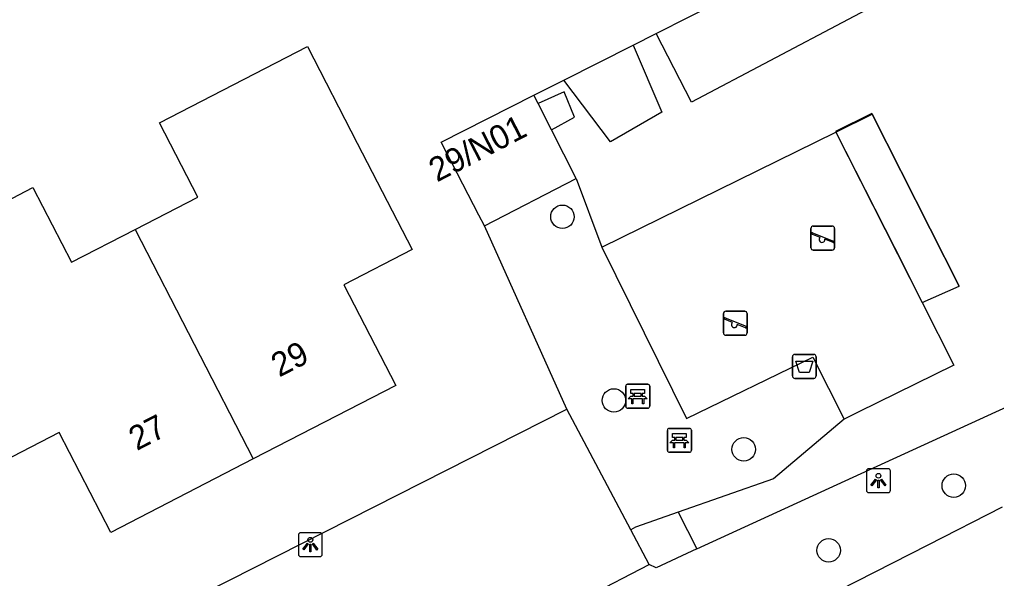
# Model space of a CAD drawing. Extents: x 162722 to 165099, y 384721 to 386283.
# Drawn here: x 163916.12 to 163956.87, y 385059.77 to 385083.1 of the extents above; entities that cross this region are included whole.
import ezdxf

# ---------------------------------------------------------------- set-up
doc = ezdxf.new("R2010")
doc.units = 0
for name, color, linetype in [('IMGEO_Afvalbak', 7, 'Continuous'), ('IMGEO_Bank', 7, 'Continuous'), ('IMGEO_Boom', 7, 'Continuous'), ('IMGEO_Groenvoorziening', 7, 'Continuous'), ('IMGEO_Haag', 7, 'Continuous'), ('IMGEO_Lichtpunt', 7, 'Continuous'), ('IMGEO_Pand', 7, 'Continuous'), ('IMGEO_Pand_nummerreeks', 7, 'Continuous'), ('IMGEO_Parkeervlak_open', 7, 'Continuous'), ('IMGEO_Speelvoorziening', 7, 'Continuous'), ('IMGEO_Voetpad_open', 7, 'Continuous')]:
    doc.layers.add(name, color=color, linetype=linetype)

msp = doc.modelspace()

# ---------------------------------------------------------------- linework, layer by layer
at = {"layer": 'IMGEO_Afvalbak'}
for p, q in [((163948.359, 385068.222), (163948.359, 385069.022)), ((163948.359, 385069.022), (163948.359, 385068.222)), ((163948.459, 385069.122), (163949.249, 385069.122)), ((163949.249, 385069.122), (163948.459, 385069.122)), ((163949.349, 385069.022), (163949.349, 385068.222)), ((163949.349, 385068.222), (163949.349, 385069.022)), ((163949.249, 385068.122), (163948.459, 385068.122)), ((163948.459, 385068.122), (163949.249, 385068.122))]:
    msp.add_line(p, q, dxfattribs=at)
msp.add_lwpolyline([(163948.502, 385068.836), (163949.206, 385068.836), (163949.057, 385068.366), (163948.651, 385068.366), (163948.502, 385068.836)], dxfattribs=at)
for centre, start, end in [((163948.459, 385069.022), 90, 180), ((163948.459, 385069.022), 90, 180), ((163949.249, 385069.022), 0, 90), ((163949.249, 385069.022), 360, 90), ((163948.459, 385068.222), 180, 270), ((163948.459, 385068.222), 180, 270), ((163949.249, 385068.222), 270, 0), ((163949.249, 385068.222), 270, 0)]:
    msp.add_arc(centre, 0.1, start, end, dxfattribs=at)
at = {"layer": 'IMGEO_Bank'}
for p, q in [((163941.406, 385066.951), (163941.406, 385067.792)), ((163941.406, 385067.792), (163941.406, 385066.951)), ((163941.481, 385067.876), (163942.322, 385067.876)), ((163942.322, 385067.876), (163941.481, 385067.876)), ((163942.406, 385067.801), (163942.406, 385066.96)), ((163942.406, 385066.96), (163942.406, 385067.801)), ((163942.103, 385067.274), (163941.71, 385067.274)), ((163941.715, 385067.382), (163941.715, 385067.488)), ((163941.759, 385067.488), (163941.759, 385067.382)), ((163942.047, 385067.494), (163941.765, 385067.494)), ((163941.765, 385067.376), (163942.047, 385067.376)), ((163942.053, 385067.382), (163942.053, 385067.488)), ((163942.097, 385067.488), (163942.097, 385067.382)), ((163942.331, 385066.876), (163941.49, 385066.876)), ((163941.49, 385066.876), (163942.331, 385066.876)), ((163943.144, 385065.111), (163943.144, 385065.952)), ((163943.144, 385065.952), (163943.144, 385065.111)), ((163943.219, 385066.036), (163944.06, 385066.036)), ((163944.06, 385066.036), (163943.219, 385066.036)), ((163944.144, 385065.961), (163944.144, 385065.12)), ((163944.144, 385065.12), (163944.144, 385065.961)), ((163943.453, 385065.542), (163943.453, 385065.648)), ((163943.497, 385065.648), (163943.497, 385065.542)), ((163943.785, 385065.654), (163943.503, 385065.654)), ((163943.503, 385065.536), (163943.785, 385065.536)), ((163943.791, 385065.542), (163943.791, 385065.648)), ((163943.835, 385065.648), (163943.835, 385065.542)), ((163943.841, 385065.434), (163943.448, 385065.434)), ((163944.069, 385065.036), (163943.228, 385065.036)), ((163943.228, 385065.036), (163944.069, 385065.036))]:
    msp.add_line(p, q, dxfattribs=at)
for points in [[(163941.709, 385067.494), (163941.623, 385067.494), (163941.623, 385067.655), (163942.186, 385067.655), (163942.186, 385067.494), (163942.103, 385067.494)], [(163941.653, 385067.274), (163941.511, 385067.274), (163941.623, 385067.376), (163941.709, 385067.376)], [(163941.703, 385067.267), (163941.703, 385067.06), (163941.66, 385067.06), (163941.66, 385067.267)], [(163942.103, 385067.376), (163942.186, 385067.376), (163942.298, 385067.274), (163942.159, 385067.274)], [(163942.153, 385067.267), (163942.153, 385067.06), (163942.109, 385067.06), (163942.109, 385067.267)], [(163943.391, 385065.434), (163943.249, 385065.434), (163943.361, 385065.536), (163943.447, 385065.536)], [(163943.447, 385065.654), (163943.361, 385065.654), (163943.361, 385065.815), (163943.924, 385065.815), (163943.924, 385065.654), (163943.841, 385065.654)], [(163943.841, 385065.536), (163943.924, 385065.536), (163944.036, 385065.434), (163943.897, 385065.434)], [(163943.441, 385065.427), (163943.441, 385065.22), (163943.398, 385065.22), (163943.398, 385065.427)], [(163943.891, 385065.427), (163943.891, 385065.22), (163943.847, 385065.22), (163943.847, 385065.427)]]:
    msp.add_lwpolyline(points, dxfattribs=at)
for centre, radius, start, end in [((163941.484, 385067.798), 0.0779, 92.4484, 184.2845), ((163941.484, 385067.798), 0.0779, 92.4484, 184.2845), ((163942.328, 385067.798), 0.0779, 2.4484, 94.2845), ((163942.328, 385067.798), 0.0779, 2.4484, 94.2845), ((163941.653, 385067.267), 0.00671, 2.8957, 87.1043), ((163941.71, 385067.267), 0.00671, 92.8957, 177.1043), ((163941.708, 385067.487), 0.00671, 2.8957, 87.1043), ((163941.708, 385067.383), 0.00671, 272.8957, 357.1043), ((163941.765, 385067.487), 0.00671, 92.8957, 177.1043), ((163941.765, 385067.383), 0.00671, 182.8957, 267.1043), ((163942.047, 385067.487), 0.00671, 2.8957, 87.1043), ((163942.047, 385067.383), 0.00671, 272.8957, 357.1043), ((163942.104, 385067.487), 0.00671, 92.8957, 177.1043), ((163942.104, 385067.383), 0.00671, 182.8957, 267.1043), ((163942.102, 385067.267), 0.00671, 2.8957, 87.1043), ((163942.159, 385067.267), 0.00671, 92.8957, 177.1043), ((163941.484, 385066.954), 0.0779, 182.4484, 274.2845), ((163941.484, 385066.954), 0.0779, 182.4484, 274.2845), ((163942.328, 385066.954), 0.0779, 272.4484, 4.2845), ((163942.328, 385066.954), 0.0779, 272.4484, 4.2845), ((163943.222, 385065.958), 0.0779, 92.4484, 184.2845), ((163943.222, 385065.958), 0.0779, 92.4484, 184.2845), ((163944.066, 385065.958), 0.0779, 2.4484, 94.2845), ((163944.066, 385065.958), 0.0779, 2.4484, 94.2845), ((163943.446, 385065.647), 0.00671, 2.8957, 87.1043), ((163943.446, 385065.543), 0.00671, 272.8957, 357.1043), ((163943.503, 385065.647), 0.00671, 92.8957, 177.1043), ((163943.503, 385065.543), 0.00671, 182.8957, 267.1043), ((163943.785, 385065.647), 0.00671, 2.8957, 87.1043), ((163943.785, 385065.543), 0.00671, 272.8957, 357.1043), ((163943.842, 385065.647), 0.00671, 92.8957, 177.1043), ((163943.842, 385065.543), 0.00671, 182.8957, 267.1043), ((163943.391, 385065.427), 0.00671, 2.8957, 87.1043), ((163943.448, 385065.427), 0.00671, 92.8957, 177.1043), ((163943.84, 385065.427), 0.00671, 2.8957, 87.1043), ((163943.897, 385065.427), 0.00671, 92.8957, 177.1043), ((163943.222, 385065.114), 0.0779, 182.4484, 274.2845), ((163943.222, 385065.114), 0.0779, 182.4484, 274.2845), ((163944.066, 385065.114), 0.0779, 272.4484, 4.2845), ((163944.066, 385065.114), 0.0779, 272.4484, 4.2845)]:
    msp.add_arc(centre, radius, start, end, dxfattribs=at)
at = {"layer": 'IMGEO_Boom'}
for centre in [(163938.763, 385074.866), (163940.912, 385067.202), (163946.327, 385065.16), (163955.089, 385063.644), (163949.869, 385060.944)]:
    msp.add_circle(centre, 0.489, dxfattribs=at)
at = {"layer": 'IMGEO_Groenvoorziening'}
for points in [[(163953.947, 385084.839), (163944.148, 385079.652), (163942.681, 385082.519)], [(163942.681, 385082.519), (163945.427, 385083.907)], [(163941.712, 385082.029), (163942.681, 385082.519)], [(163938.823, 385080.568), (163941.712, 385082.029)], [(163941.712, 385082.029), (163942.908, 385079.238), (163940.769, 385077.997), (163938.823, 385080.568)], [(163937.574, 385079.937), (163938.823, 385080.568)], [(163950.173, 385078.399), (163951.683, 385079.142), (163955.32, 385071.967)], [(163940.409, 385073.595), (163950.173, 385078.399)], [(163950.173, 385078.399), (163950.173, 385078.399)], [(163950.173, 385078.399), (163953.776, 385071.287)], [(163939.334, 385076.457), (163940.409, 385073.595)], [(163938.946, 385066.833), (163935.508, 385074.482)], [(163940.409, 385073.595), (163943.946, 385066.445), (163949.212, 385069.011), (163950.523, 385066.423)], [(163953.776, 385071.287), (163955.099, 385068.674), (163951.1, 385066.707), (163950.523, 385066.423)], [(163944.367, 385061.012), (163952.229, 385064.609), (163966.391, 385071.088), (163968.192, 385068.42)], [(163950.523, 385066.423), (163947.565, 385063.927), (163943.589, 385062.535)]]:
    msp.add_lwpolyline(points, dxfattribs=at)
at = {"layer": 'IMGEO_Haag'}
for points in [[(163955.32, 385071.967), (163951.668, 385079.172), (163950.161, 385078.423), (163950.173, 385078.399)], [(163950.173, 385078.399), (163952.614, 385073.581), (163953.776, 385071.287)], [(163953.776, 385071.287), (163955.32, 385071.967)]]:
    msp.add_lwpolyline(points, dxfattribs=at)
at = {"layer": 'IMGEO_Lichtpunt'}
for p, q in [((163952.351, 385064.353), (163951.543, 385064.353)), ((163952.351, 385064.353), (163951.543, 385064.353)), ((163951.449, 385064.258), (163951.449, 385063.451)), ((163951.449, 385064.258), (163951.449, 385063.451)), ((163952.445, 385063.451), (163952.445, 385064.258)), ((163952.445, 385063.451), (163952.445, 385064.258)), ((163951.543, 385063.357), (163952.351, 385063.357)), ((163951.543, 385063.357), (163952.351, 385063.357)), ((163927.748, 385061.586), (163927.748, 385060.779)), ((163927.748, 385061.586), (163927.748, 385060.779)), ((163928.65, 385061.681), (163927.842, 385061.681)), ((163928.65, 385061.681), (163927.842, 385061.681)), ((163928.744, 385060.779), (163928.744, 385061.586)), ((163928.744, 385060.779), (163928.744, 385061.586)), ((163927.842, 385060.685), (163928.65, 385060.685)), ((163927.842, 385060.685), (163928.65, 385060.685))]:
    msp.add_line(p, q, dxfattribs=at)
for points in [[(163951.823, 385063.922), (163951.862, 385063.894), (163951.674, 385063.632), (163951.636, 385063.659), (163951.823, 385063.922)], [(163952.035, 385063.894), (163952.073, 385063.921), (163952.26, 385063.659), (163952.221, 385063.631), (163952.035, 385063.894)], [(163951.925, 385063.874), (163951.972, 385063.874), (163951.972, 385063.552), (163951.925, 385063.552), (163951.925, 385063.874)], [(163928.122, 385061.25), (163928.161, 385061.222), (163927.973, 385060.96), (163927.935, 385060.987), (163928.122, 385061.25)], [(163928.224, 385061.202), (163928.271, 385061.202), (163928.271, 385060.88), (163928.224, 385060.88), (163928.224, 385061.202)], [(163928.334, 385061.222), (163928.372, 385061.249), (163928.559, 385060.987), (163928.52, 385060.959), (163928.334, 385061.222)]]:
    msp.add_lwpolyline(points, dxfattribs=at)
for centre in [(163951.948, 385064.056), (163928.247, 385061.384)]:
    msp.add_circle(centre, 0.0994, dxfattribs=at)
for centre, start, end in [((163951.543, 385064.258), 90, 180), ((163951.543, 385064.258), 90, 180), ((163952.351, 385064.258), 0, 90), ((163952.351, 385064.258), 0, 90), ((163951.543, 385063.451), 180, 270), ((163951.543, 385063.451), 180, 270), ((163952.351, 385063.451), 270, 0), ((163952.351, 385063.451), 270, 360), ((163927.842, 385061.586), 90, 180), ((163927.842, 385061.586), 90, 180), ((163928.65, 385061.586), 0, 90), ((163928.65, 385061.586), 0, 90), ((163927.842, 385060.779), 180, 270), ((163927.842, 385060.779), 180, 270), ((163928.65, 385060.779), 270, 0), ((163928.65, 385060.779), 270, 360)]:
    msp.add_arc(centre, 0.0946, start, end, dxfattribs=at)
at = {"layer": 'IMGEO_Pand'}
for points in [[(163920.934, 385074.332), (163923.551, 385075.682), (163921.948, 385078.788), (163928.127, 385081.975), (163930.207, 385077.941), (163932.499, 385073.497), (163929.642, 385072.024), (163931.809, 385067.822), (163925.868, 385064.758)], [(163935.508, 385074.482), (163935.277, 385074.929), (163933.702, 385077.979), (163937.574, 385079.937)], [(163937.748, 385079.592), (163937.574, 385079.937)], [(163938.305, 385078.491), (163937.748, 385079.592)], [(163939.334, 385076.457), (163938.305, 385078.491)], [(163935.508, 385074.482), (163939.334, 385076.457)], [(163925.868, 385064.758), (163919.927, 385061.695), (163917.775, 385065.867), (163914.617, 385064.238), (163910.224, 385072.757), (163914.668, 385075.049), (163916.677, 385076.085), (163918.286, 385072.966), (163920.934, 385074.332)], [(163920.934, 385074.332), (163925.868, 385064.758)], [(163957.108, 385062.751), (163954.007, 385061.166), (163949.555, 385058.889)]]:
    msp.add_lwpolyline(points, dxfattribs=at)
at = {"layer": 'IMGEO_Parkeervlak_open'}
for points in [[(163906.693, 385073.366), (163915.816, 385055.107), (163938.946, 385066.833)], [(163941.615, 385061.804), (163938.946, 385066.833)], [(163940.84, 385056.735), (163939.815, 385059.02), (163942.387, 385060.349)]]:
    msp.add_lwpolyline(points, dxfattribs=at)
at = {"layer": 'IMGEO_Speelvoorziening'}
for p, q in [((163949.131, 385073.576), (163949.131, 385074.376)), ((163949.131, 385074.376), (163949.131, 385073.576)), ((163949.514, 385074.004), (163949.175, 385074.141)), ((163949.2, 385074.201), (163950.076, 385073.848)), ((163949.231, 385074.476), (163950.021, 385074.476)), ((163950.021, 385074.476), (163949.231, 385074.476)), ((163950.121, 385074.376), (163950.121, 385073.576)), ((163950.121, 385073.576), (163950.121, 385074.376)), ((163950.052, 385073.788), (163949.712, 385073.925)), ((163950.021, 385073.476), (163949.231, 385073.476)), ((163949.231, 385073.476), (163950.021, 385073.476)), ((163945.579, 385070.923), (163946.369, 385070.923)), ((163946.369, 385070.923), (163945.579, 385070.923)), ((163945.479, 385070.023), (163945.479, 385070.823)), ((163945.479, 385070.823), (163945.479, 385070.023)), ((163945.862, 385070.451), (163945.523, 385070.588)), ((163945.548, 385070.648), (163946.424, 385070.295)), ((163946.469, 385070.823), (163946.469, 385070.023)), ((163946.469, 385070.023), (163946.469, 385070.823)), ((163946.4, 385070.235), (163946.06, 385070.372)), ((163946.369, 385069.923), (163945.579, 385069.923)), ((163945.579, 385069.923), (163946.369, 385069.923))]:
    msp.add_line(p, q, dxfattribs=at)
for centre, radius, start, end in [((163949.231, 385074.376), 0.1, 90, 180), ((163949.231, 385074.376), 0.1, 90, 180), ((163949.188, 385074.171), 0.0327, 68.078, 248.078), ((163950.021, 385074.376), 0.1, 0, 90), ((163950.021, 385074.376), 0.1, 360, 90), ((163949.593, 385073.914), 0.12, 130.9928, 5.1632), ((163950.064, 385073.818), 0.0327, 248.078, 68.078), ((163949.231, 385073.576), 0.1, 180, 270), ((163949.231, 385073.576), 0.1, 180, 270), ((163950.021, 385073.576), 0.1, 270, 0), ((163950.021, 385073.576), 0.1, 270, 0), ((163945.579, 385070.823), 0.1, 90, 180), ((163945.579, 385070.823), 0.1, 90, 180), ((163946.369, 385070.823), 0.1, 0, 90), ((163946.369, 385070.823), 0.1, 360, 90), ((163945.536, 385070.618), 0.0327, 68.078, 248.078), ((163945.941, 385070.361), 0.12, 130.9928, 5.1632), ((163945.579, 385070.023), 0.1, 180, 270), ((163945.579, 385070.023), 0.1, 180, 270), ((163946.369, 385070.023), 0.1, 270, 0), ((163946.369, 385070.023), 0.1, 270, 0), ((163946.412, 385070.265), 0.0327, 248.078, 68.078)]:
    msp.add_arc(centre, radius, start, end, dxfattribs=at)
at = {"layer": 'IMGEO_Voetpad_open'}
for points in [[(163938.305, 385078.491), (163939.27, 385079.029), (163938.843, 385080.073), (163937.748, 385079.592)], [(163943.589, 385062.535), (163941.812, 385061.913), (163941.615, 385061.804)], [(163943.589, 385062.535), (163944.367, 385061.012)], [(163942.387, 385060.349), (163941.615, 385061.804)], [(163944.367, 385061.012), (163942.68, 385060.208), (163942.387, 385060.349)]]:
    msp.add_lwpolyline(points, dxfattribs=at)

# ---------------------------------------------------------------- texts
at = {"layer": 'IMGEO_Pand_nummerreeks'}
for s, rotation, p in [('29/N01', 27.2893, (163933.528, 385076.294)), ('29', 27.2781, (163926.948, 385068.151)), ('27', 27.2781, (163921.007, 385065.087))]:
    msp.add_text(s, height=1, rotation=rotation, dxfattribs=at).set_placement(p)

doc.saveas('drawing.dxf')
